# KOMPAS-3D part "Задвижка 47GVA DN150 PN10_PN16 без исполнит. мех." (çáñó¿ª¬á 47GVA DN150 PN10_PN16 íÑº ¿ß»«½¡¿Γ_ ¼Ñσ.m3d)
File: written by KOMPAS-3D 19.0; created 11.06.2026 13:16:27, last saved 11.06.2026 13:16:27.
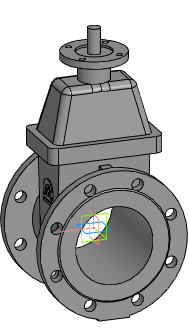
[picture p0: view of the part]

Document properties: Автор: Евгений; Полное имя файла: Z:\3.Личные\kachalov\001_3d для проектировщиков\2.2 Тип 47GVA, 47GVA.Z\_stp\_stp_Задвижка 47GVA DN40-DN1000 без исп.мех\Задвижка 47GVA DN150 PN10_PN16 без исполнит_ мех.m3d

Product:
- Part/product: Задвижка 47GVA DN150 PN10_PN16 без исполнит. мех.

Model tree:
1. Операция без истории:1  (labels: Задвижка 47GVA DN150 PN10_PN16 без исполнит. мех.)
